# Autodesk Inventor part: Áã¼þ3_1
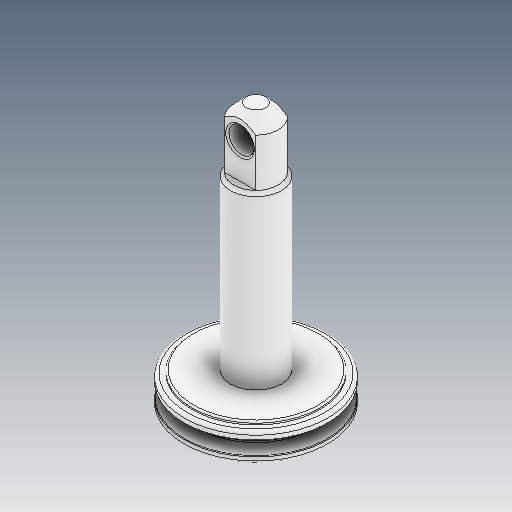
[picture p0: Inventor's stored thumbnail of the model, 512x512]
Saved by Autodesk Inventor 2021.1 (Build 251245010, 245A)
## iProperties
Created: 2021-05
Part Number: Áã¼þ3_1
Material: Ogólny
Document SubType Name: Modeling
Designer: user
Density: 1 g/cm^3
Appearance: Domyślna
Author: user
Revision Number: ÈÎºÎ
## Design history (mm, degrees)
feature "ÊäÈë1"
node "Bryła1"
